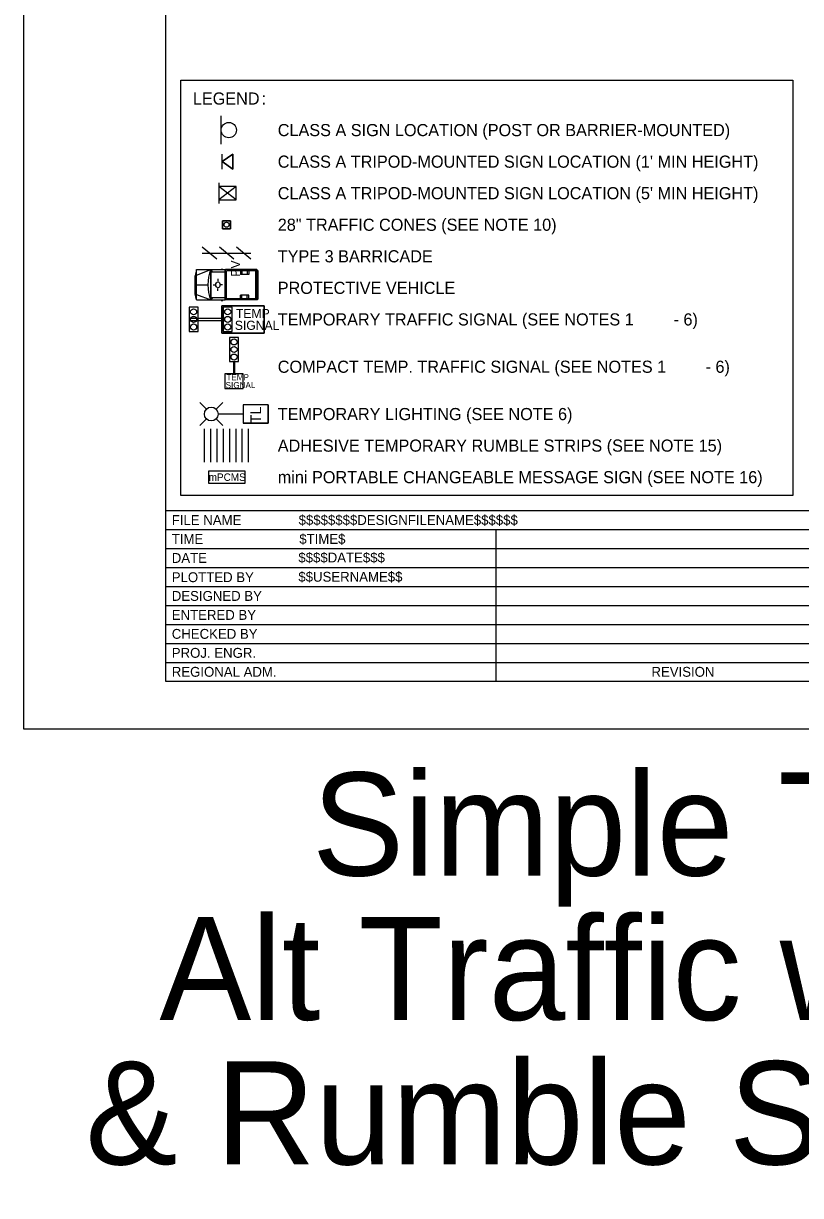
# Model space of a CAD drawing. Extents: x 99977 to 100176, y 99905 to 100011.
# Drawn here: x 100039.06 to 100044.19, y 99906.61 to 99914.34 of the extents above; entities that cross this region are included whole.
import ezdxf

# ---------------------------------------------------------------- set-up
doc = ezdxf.new("R2010")
doc.units = 0
for name, color, linetype in [('SH_GI_PlotLimits', 7, 'Continuous'), ('SH_GI_SheetBorder', 7, 'Continuous'), ('SH_GI_SheetLocationText', 7, 'Continuous'), ('SH_GI_SheetTextInCells', 7, 'Continuous'), ('SH_GI_TitleBlockText', 7, 'Continuous'), ('TR_WZ_BarricadeType3', 7, 'Continuous'), ('TR_WZ_PortableChangeMessageSign', 7, 'Continuous'), ('TR_WZ_PortableLightStandard', 7, 'Continuous'), ('TR_WZ_PortableSignMount5ftMinBlk-Wht', 7, 'Continuous'), ('TR_WZ_PortableSignMountBlk-Wht', 7, 'Continuous'), ('TR_WZ_ProtectiveVehicle', 7, 'Continuous'), ('TR_WZ_Sign', 7, 'Continuous'), ('TR_WZ_TempSignal', 7, 'Continuous'), ('TR_WZ_TrafficCone', 7, 'Continuous'), ('TR_WZ_WorkZoneDetails', 7, 'Continuous'), ('TR_WZ_WorkZoneTextCurrent', 7, 'Continuous')]:
    doc.layers.add(name, color=color, linetype=linetype)

msp = doc.modelspace()

# ---------------------------------------------------------------- linework, layer by layer
at = {"layer": 'SH_GI_PlotLimits'}
msp.add_lwpolyline([(100039.0625, 99909.6875), (100056.0625, 99909.6875), (100056.0625, 99920.6875), (100039.0625, 99920.6875)], close=True, dxfattribs=at)
at = {"layer": 'SH_GI_SheetBorder'}
for p, q in [((100040, 99920.375), (100040, 99910)), ((100040, 99911.1259), (100055.75, 99911.1259)), ((100040, 99911.0008), (100047.4566, 99911.0008)), ((100042.179, 99911.0008), (100042.179, 99910)), ((100040, 99910.8757), (100042.1821, 99910.8757)), ((100042.1821, 99910.8757), (100045.4466, 99910.8757)), ((100040, 99910.7506), (100042.1821, 99910.7506)), ((100042.1821, 99910.7506), (100045.4466, 99910.7506)), ((100040, 99910.6255), (100045.4466, 99910.6255)), ((100040, 99910.5004), (100045.4466, 99910.5004)), ((100040, 99910.3753), (100045.4466, 99910.3753)), ((100040, 99910.2502), (100045.4466, 99910.2502)), ((100040, 99910.1251), (100045.4466, 99910.1251)), ((100040, 99910), (100055.75, 99910))]:
    msp.add_line(p, q, dxfattribs=at)
at = {"layer": 'TR_WZ_BarricadeType3'}
for p, q in [((100040.3381, 99912.7823), (100040.2425, 99912.8615)), ((100040.2425, 99912.8219), (100040.5625, 99912.8219)), ((100040.4503, 99912.7823), (100040.3547, 99912.8615)), ((100040.5625, 99912.7823), (100040.4669, 99912.8615))]:
    msp.add_line(p, q, dxfattribs=at)
at = {"layer": 'TR_WZ_PortableChangeMessageSign'}
msp.add_lwpolyline([(100040.2841, 99911.3059), (100040.5241, 99911.3059), (100040.5241, 99911.3859), (100040.2841, 99911.3859)], close=True, dxfattribs=at)
msp.add_lwpolyline([(100040.2841, 99911.3059), (100040.5241, 99911.3059), (100040.5241, 99911.3859), (100040.2841, 99911.3859), (100040.2841, 99911.3059)], dxfattribs=at)
at = {"layer": 'TR_WZ_PortableLightStandard'}
for p, q in [((100040.2692, 99911.7943), (100040.2261, 99911.8373)), ((100040.3339, 99911.7943), (100040.377, 99911.8373)), ((100040.6777, 99911.8219), (100040.5117, 99911.8219)), ((100040.5117, 99911.8219), (100040.5117, 99911.7019)), ((100040.6777, 99911.8219), (100040.5117, 99911.8219)), ((100040.6777, 99911.8219), (100040.6777, 99911.7019)), ((100040.2692, 99911.7295), (100040.2261, 99911.6864)), ((100040.3339, 99911.7295), (100040.377, 99911.6864)), ((100040.5117, 99911.7619), (100040.3473, 99911.7619)), ((100040.6777, 99911.7019), (100040.5117, 99911.7019)), ((100040.5117, 99911.7019), (100040.6777, 99911.7019))]:
    msp.add_line(p, q, dxfattribs=at)
for points in [[(100040.5117, 99911.8219), (100040.5117, 99911.7619), (100040.5117, 99911.7019)], [(100040.6777, 99911.7019), (100040.6777, 99911.7619), (100040.6777, 99911.8219)]]:
    msp.add_lwpolyline(points, dxfattribs=at)
msp.add_circle((100040.3015, 99911.7619), 0.0457, dxfattribs=at)
msp.add_circle((100040.3015, 99911.7619), 0.0457, dxfattribs=at)
at = {"layer": 'TR_WZ_PortableSignMount5ftMinBlk-Wht'}
for p, q in [((100040.3512, 99913.2869), (100040.3512, 99913.1489)), ((100040.4663, 99913.1731), (100040.3512, 99913.2627)), ((100040.4663, 99913.2627), (100040.3512, 99913.1731)), ((100040.4088, 99913.2179), (100040.4088, 99913.2179)), ((100040.4089, 99913.2178), (100040.4089, 99913.2178))]:
    msp.add_line(p, q, dxfattribs=at)
msp.add_lwpolyline([(100040.4663, 99913.1731), (100040.4663, 99913.2627), (100040.3512, 99913.2627), (100040.3512, 99913.1731)], close=True, dxfattribs=at)
at = {"layer": 'TR_WZ_PortableSignMountBlk-Wht'}
msp.add_line((100040.3728, 99913.3759), (100040.3728, 99913.4759), dxfattribs=at)
msp.add_lwpolyline([(100040.3728, 99913.4258), (100040.4447, 99913.4759), (100040.4447, 99913.3759)], close=True, dxfattribs=at)
at = {"layer": 'TR_WZ_ProtectiveVehicle'}
for p, q in [((100040.2036, 99912.7139), (100040.1944, 99912.6735)), ((100040.2036, 99912.5139), (100040.2036, 99912.7139)), ((100040.2036, 99912.7139), (100040.3925, 99912.7139)), ((100040.2036, 99912.6773), (100040.2981, 99912.7139)), ((100040.2981, 99912.5139), (100040.2981, 99912.7139)), ((100040.2998, 99912.5139), (100040.2998, 99912.7139)), ((100040.3098, 99912.6984), (100040.2998, 99912.7139)), ((100040.3668, 99912.7167), (100040.3781, 99912.7167)), ((100040.3925, 99912.5139), (100040.3925, 99912.7139)), ((100040.601, 99912.7139), (100040.3953, 99912.7139)), ((100040.3953, 99912.5139), (100040.3953, 99912.7139)), ((100040.601, 99912.5139), (100040.601, 99912.7139)), ((100040.1944, 99912.5543), (100040.1944, 99912.6735)), ((100040.2998, 99912.6984), (100040.3925, 99912.6984)), ((100040.3458, 99912.6524), (100040.3455, 99912.6373)), ((100040.5952, 99912.7059), (100040.4011, 99912.7059)), ((100040.4011, 99912.5219), (100040.4011, 99912.7059)), ((100040.4938, 99912.7059), (100040.4938, 99912.6829)), ((100040.5488, 99912.6829), (100040.4938, 99912.6829)), ((100040.5038, 99912.7059), (100040.5038, 99912.6829)), ((100040.5378, 99912.7059), (100040.5378, 99912.6829)), ((100040.5488, 99912.7059), (100040.5488, 99912.6829)), ((100040.5952, 99912.5219), (100040.5952, 99912.7059)), ((100040.6061, 99912.7106), (100040.6017, 99912.7106)), ((100040.6017, 99912.5172), (100040.6017, 99912.7106)), ((100040.6106, 99912.5233), (100040.6106, 99912.7045)), ((100040.2036, 99912.6139), (100040.2795, 99912.6139)), ((100040.315, 99912.6138), (100040.3276, 99912.6138)), ((100040.3451, 99912.5743), (100040.3451, 99912.5904)), ((100040.3592, 99912.6142), (100040.3592, 99912.6142)), ((100040.376, 99912.6147), (100040.3611, 99912.6143)), ((100040.6106, 99912.628), (100040.6017, 99912.6242)), ((100040.6106, 99912.5998), (100040.6017, 99912.6036)), ((100040.6082, 99912.6139), (100040.6041, 99912.6139)), ((100040.6061, 99912.6111), (100040.6061, 99912.6167)), ((100040.2036, 99912.5139), (100040.1944, 99912.5543)), ((100040.2036, 99912.5505), (100040.2981, 99912.5139)), ((100040.2036, 99912.5139), (100040.3925, 99912.5139)), ((100040.2998, 99912.5139), (100040.3118, 99912.5294)), ((100040.2998, 99912.5294), (100040.3925, 99912.5294)), ((100040.3668, 99912.5111), (100040.3781, 99912.5111)), ((100040.601, 99912.5139), (100040.3953, 99912.5139)), ((100040.5952, 99912.5219), (100040.4011, 99912.5219)), ((100040.5488, 99912.5449), (100040.4938, 99912.5449)), ((100040.4938, 99912.5219), (100040.4938, 99912.5449)), ((100040.5038, 99912.5219), (100040.5038, 99912.5449)), ((100040.5378, 99912.5219), (100040.5378, 99912.5449)), ((100040.5488, 99912.5219), (100040.5488, 99912.5449)), ((100040.6061, 99912.5172), (100040.6017, 99912.5172))]:
    msp.add_line(p, q, dxfattribs=at)
for centre, major_axis, start_param, end_param in [((100040.4331, 99912.6139), (0, -0.2099), 4.215852, 5.209111), ((100040.6061, 99912.7045), (0, 0.0061), 4.712389, 6.283185), ((100040.6061, 99912.5233), (0, -0.0061), 6.283185, 7.853982)]:
    msp.add_ellipse(centre, major_axis=major_axis, ratio=0.73155, start_param=start_param, end_param=end_param, dxfattribs=at)
for centre, major_axis in [((100040.3451, 99912.6139), (0, 0.0193)), ((100040.6061, 99912.6139), (0, 0.00282))]:
    msp.add_ellipse(centre, major_axis=major_axis, ratio=0.73155, dxfattribs=at)
at = {"layer": 'TR_WZ_Sign'}
msp.add_line((100040.3668, 99913.5407), (100040.3668, 99913.7271), dxfattribs=at)
msp.add_circle((100040.4172, 99913.634), 0.0504, dxfattribs=at)
msp.add_circle((100040.4172, 99913.634), 0.0504, dxfattribs=at)
at = {"layer": 'TR_WZ_TempSignal'}
for p, q in [((100040.215, 99912.4658), (100040.1551, 99912.4658)), ((100040.1551, 99912.4658), (100040.1551, 99912.306)), ((100040.215, 99912.306), (100040.215, 99912.4658)), ((100040.3701, 99912.4759), (100040.6501, 99912.4759)), ((100040.3701, 99912.2959), (100040.3701, 99912.4759)), ((100040.6501, 99912.4759), (100040.3701, 99912.4759)), ((100040.3701, 99912.4759), (100040.3701, 99912.3926)), ((100040.44, 99912.4658), (100040.3801, 99912.4658)), ((100040.3801, 99912.4658), (100040.3801, 99912.306)), ((100040.44, 99912.306), (100040.44, 99912.4658)), ((100040.6501, 99912.4759), (100040.6501, 99912.2959)), ((100040.6501, 99912.2959), (100040.6501, 99912.4759)), ((100040.3701, 99912.3926), (100040.1551, 99912.3926)), ((100040.1551, 99912.3926), (100040.1551, 99912.3792)), ((100040.1551, 99912.3792), (100040.3701, 99912.3792)), ((100040.3701, 99912.3792), (100040.3701, 99912.3926)), ((100040.3701, 99912.3926), (100040.3701, 99912.3792)), ((100040.3701, 99912.3792), (100040.3701, 99912.2959)), ((100040.1551, 99912.306), (100040.215, 99912.306)), ((100040.6501, 99912.2959), (100040.3701, 99912.2959)), ((100040.3701, 99912.2959), (100040.6501, 99912.2959)), ((100040.3801, 99912.306), (100040.44, 99912.306)), ((100040.4819, 99912.2672), (100040.422, 99912.2672)), ((100040.422, 99912.2672), (100040.422, 99912.1075)), ((100040.4819, 99912.1075), (100040.4819, 99912.2672)), ((100040.422, 99912.1075), (100040.4819, 99912.1075)), ((100040.5119, 99912.0275), (100040.3919, 99912.0275)), ((100040.3919, 99912.0275), (100040.3919, 99911.983)), ((100040.5119, 99911.9297), (100040.5119, 99912.0275)), ((100040.3919, 99911.983), (100040.3919, 99911.9742)), ((100040.3919, 99911.9742), (100040.3919, 99911.9297)), ((100040.3919, 99911.9297), (100040.5119, 99911.9297))]:
    msp.add_line(p, q, dxfattribs=at)
for points in [[(100040.215, 99912.4658), (100040.1551, 99912.4658), (100040.1551, 99912.306), (100040.215, 99912.306), (100040.215, 99912.4658)], [(100040.44, 99912.4658), (100040.3801, 99912.4658), (100040.3801, 99912.306), (100040.44, 99912.306), (100040.44, 99912.4658)], [(100040.4819, 99912.2672), (100040.422, 99912.2672), (100040.422, 99912.1075), (100040.4819, 99912.1075), (100040.4819, 99912.2672)], [(100040.5119, 99912.0275), (100040.3919, 99912.0275), (100040.3919, 99911.9297), (100040.5119, 99911.9297), (100040.5119, 99912.0275)]]:
    msp.add_lwpolyline(points, dxfattribs=at)
msp.add_lwpolyline([(100040.4494, 99912.1075), (100040.4544, 99912.1075), (100040.4544, 99912.0275), (100040.4494, 99912.0275)], close=True, dxfattribs=at)
for centre in [(100040.1851, 99912.4358), (100040.1851, 99912.4358), (100040.1851, 99912.3859), (100040.1851, 99912.3859), (100040.4101, 99912.4358), (100040.4101, 99912.4358), (100040.4101, 99912.3859), (100040.4101, 99912.3859), (100040.1851, 99912.336), (100040.1851, 99912.336), (100040.4101, 99912.336), (100040.4101, 99912.336), (100040.4519, 99912.2373), (100040.4519, 99912.2373), (100040.4519, 99912.1874), (100040.4519, 99912.1874), (100040.4519, 99912.1374), (100040.4519, 99912.1374)]:
    msp.add_circle(centre, 0.02, dxfattribs=at)
at = {"layer": 'TR_WZ_TrafficCone'}
for points in [[(100040.3759, 99913.0366), (100040.4293, 99913.0366), (100040.4293, 99912.9832), (100040.3759, 99912.9832), (100040.3759, 99913.0366)], [(100040.3759, 99912.9832), (100040.4293, 99912.9832), (100040.4293, 99913.0366), (100040.3759, 99913.0366), (100040.3759, 99912.9832)]]:
    msp.add_lwpolyline(points, dxfattribs=at)
msp.add_circle((100040.4026, 99913.0099), 0.0167, dxfattribs=at)
at = {"layer": 'TR_WZ_WorkZoneDetails'}
for p, q in [((100040.2574, 99911.4439), (100040.2574, 99911.6639)), ((100040.2991, 99911.4439), (100040.2991, 99911.6639)), ((100040.3403, 99911.4439), (100040.3403, 99911.6639)), ((100040.382, 99911.4439), (100040.382, 99911.6639)), ((100040.4232, 99911.4439), (100040.4232, 99911.6639)), ((100040.4649, 99911.4439), (100040.4649, 99911.6639)), ((100040.5061, 99911.4439), (100040.5061, 99911.6639)), ((100040.5478, 99911.4439), (100040.5478, 99911.6639))]:
    msp.add_line(p, q, dxfattribs=at)
msp.add_lwpolyline([(100040.4447, 99913.3759), (100040.4447, 99913.4759), (100040.3728, 99913.4258), (100040.4447, 99913.3759)], dxfattribs=at)
at = {"layer": 'TR_WZ_WorkZoneTextCurrent'}
msp.add_lwpolyline([(100040.1, 99913.9619), (100044.1384, 99913.9619), (100044.1384, 99911.2259), (100040.1, 99911.2259)], close=True, dxfattribs=at)

# ---------------------------------------------------------------- texts
at = {"layer": 'SH_GI_SheetLocationText'}
for s, p in [('Simple', (100040.9664, 99908.7191)), (' Temp Signal-Controlled', (100043.7893, 99908.7191)), ('Alt Traffic w/ Channelization Devices', (100039.9592, 99907.7671)), ('& Rumble Strips (65, Trucks 60 mph)', (100039.4717, 99906.8151))]:
    msp.add_text(s, height=0.68, dxfattribs=at).set_placement(p)
at = {"layer": 'SH_GI_SheetTextInCells'}
for s, height, p in [('FILE NAME', 0.06505, (100040.041, 99911.0308)), ('TIME', 0.06505, (100040.041, 99910.9057)), ('DATE', 0.06505, (100040.041, 99910.7806)), ('PLOTTED BY', 0.06505, (100040.041, 99910.6538)), ('DESIGNED BY', 0.065052, (100040.041, 99910.5304)), ('ENTERED BY', 0.06505, (100040.041, 99910.4053)), ('CHECKED BY', 0.06505, (100040.041, 99910.2802)), ('PROJ. ENGR.', 0.065052, (100040.041, 99910.1551)), ('REGIONAL ADM.', 0.065052, (100040.041, 99910.03)), ('REVISION', 0.06505, (100043.2048, 99910.03))]:
    msp.add_text(s, height=height, dxfattribs=at).set_placement(p)
at = {"layer": 'SH_GI_TitleBlockText'}
for s, height, p in [('$$$$$$$$DESIGNFILENAME$$$$$$', 0.065052, (100040.8775, 99911.0308)), ('$TIME$', 0.06505, (100040.882, 99910.9059)), ('$$$$DATE$$$', 0.065052, (100040.8759, 99910.7835)), ('$$USERNAME$$', 0.065052, (100040.8759, 99910.6567))]:
    msp.add_text(s, height=height, dxfattribs=at).set_placement(p)
at = {"layer": 'TR_WZ_PortableChangeMessageSign'}
msp.add_text('mPCMS', height=0.04909, rotation=360, dxfattribs=at).set_placement((100040.2845, 99911.3214))
at = {"layer": 'TR_WZ_PortableLightStandard'}
msp.add_text('TL', height=0.07, rotation=90, dxfattribs=at).set_placement((100040.6297, 99911.7017))
at = {"layer": 'TR_WZ_ProtectiveVehicle'}
msp.add_text('PV', height=0.06, rotation=90, dxfattribs=at).set_placement((100040.4913, 99912.6677))
at = {"layer": 'TR_WZ_TempSignal'}
for s, height, p in [('TEMP', 0.06, (100040.4641, 99912.3949)), ('SIGNAL', 0.06, (100040.4567, 99912.3169)), ('TEMP', 0.04, (100040.4013, 99911.9846)), ('SIGNAL', 0.04, (100040.3963, 99911.9326))]:
    msp.add_text(s, height=height, dxfattribs=at).set_placement(p)
at = {"layer": 'TR_WZ_WorkZoneTextCurrent'}
for s, p in [('LEGEND', (100040.18, 99913.8019)), (':', (100040.6328, 99913.8019)), ('CLASS A SIGN LOCATION (POST OR BARRIER-MOUNTED)', (100040.74, 99913.5939)), ("CLASS A TRIPOD-MOUNTED SIGN LOCATION (1' MIN HEIGHT)", (100040.74, 99913.3859)), ("CLASS A TRIPOD-MOUNTED SIGN LOCATION (5' MIN HEIGHT)", (100040.74, 99913.1779)), ('28" TRAFFIC CONES (SEE NOTE 10)', (100040.74, 99912.9699)), ('TYPE 3 BARRICADE', (100040.74, 99912.7619)), ('PROTECTIVE VEHICLE', (100040.74, 99912.5539)), ('TEMPORARY TRAFFIC SIGNAL (SEE NOTES 1', (100040.74, 99912.3459)), ('- 6)', (100043.3504, 99912.3459)), ('COMPACT TEMP. TRAFFIC SIGNAL (SEE NOTES 1', (100040.74, 99912.0339)), ('- 6)', (100043.5616, 99912.0339)), ('TEMPORARY LIGHTING (SEE NOTE 6)', (100040.74, 99911.7219)), ('ADHESIVE TEMPORARY RUMBLE STRIPS (SEE NOTE 15)', (100040.74, 99911.5139)), ('mini PORTABLE CHANGEABLE MESSAGE SIGN (SEE NOTE 16)', (100040.74, 99911.3059))]:
    msp.add_text(s, height=0.08, rotation=360, dxfattribs=at).set_placement(p)

doc.saveas('drawing.dxf')
